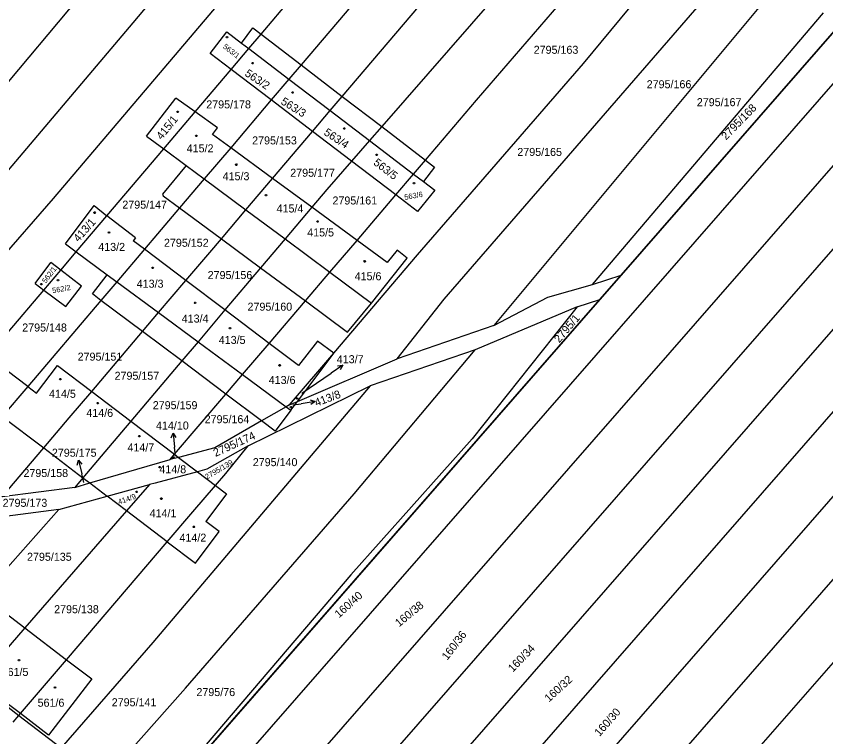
# Model space of a CAD drawing. Extents: x -580630 to -576196, y -1189024 to -1183567.
# Drawn here: x -578865 to -578693.1, y -1186221.6 to -1186068.5 of the extents above; entities that cross this region are included whole.
import ezdxf

# ---------------------------------------------------------------- set-up
doc = ezdxf.new("R2010")
doc.units = 0
for name, color, linetype in [('Vrstva 1', 7, 'Continuous'), ('Vrstva 16', 7, 'Continuous'), ('Vrstva 18', 7, 'Continuous'), ('Vrstva 19', 7, 'Continuous'), ('Vrstva 25', 7, 'Continuous'), ('Vrstva 4', 7, 'Continuous'), ('Vrstva 6', 7, 'Continuous'), ('Vrstva 63', 7, 'Continuous')]:
    doc.layers.add(name, color=color, linetype=linetype)

msp = doc.modelspace()

# ---------------------------------------------------------------- linework, layer by layer
at = {"layer": 'Vrstva 1'}
for p, q in [((-578817.1, -1186074.27), (-578814.71, -1186071.04)), ((-578814.71, -1186071.04), (-578812.98, -1186072.37)), ((-578736.53, -1186123.56), (-578690.23, -1186070.53)), ((-578898.26, -1186319.71), (-578682.45, -1186072.52)), ((-578823.75, -1186076.47), (-578820.28, -1186071.85)), ((-578820.28, -1186071.85), (-578817.1, -1186074.27)), ((-578812.98, -1186072.37), (-578804.48, -1186078.89)), ((-578819.32, -1186079.85), (-578823.75, -1186076.47)), ((-578810.8, -1186086.34), (-578819.32, -1186079.85)), ((-578804.48, -1186078.89), (-578795.74, -1186085.59)), ((-578673.98, -1186080.14), (-578889.37, -1186326.86)), ((-578837.31, -1186094.03), (-578831.04, -1186085.95)), ((-578826.97, -1186088.87), (-578831.04, -1186085.95)), ((-578802.05, -1186093.01), (-578810.8, -1186086.34)), ((-578795.74, -1186085.59), (-578787.37, -1186092.01)), ((-578880.26, -1186334.2), (-578664.84, -1186087.45)), ((-578822.23, -1186092.27), (-578826.97, -1186088.87)), ((-578823.3, -1186093.65), (-578822.23, -1186092.27)), ((-578819.42, -1186096.5), (-578823.3, -1186093.65)), ((-578793.75, -1186099.33), (-578802.05, -1186093.01)), ((-578787.37, -1186092.01), (-578778.08, -1186099.13)), ((-578656.06, -1186094.36), (-578871.56, -1186341.19)), ((-578837.31, -1186094.03), (-578833.65, -1186096.74)), ((-578833.65, -1186096.74), (-578828.87, -1186100.28)), ((-578810.54, -1186103.01), (-578819.42, -1186096.5)), ((-578828.87, -1186100.28), (-578833.87, -1186106.34)), ((-578784.35, -1186106.49), (-578793.75, -1186099.33)), ((-578778.08, -1186099.13), (-578776.12, -1186100.63)), ((-578646.98, -1186101.49), (-578862.56, -1186348.43)), ((-578776.12, -1186100.63), (-578778.47, -1186103.69)), ((-578802.19, -1186109.13), (-578810.54, -1186103.01)), ((-578778.47, -1186103.69), (-578776.08, -1186105.49)), ((-578776.08, -1186105.49), (-578779.75, -1186110)), ((-578833.87, -1186106.34), (-578833.76, -1186106.68)), ((-578833.76, -1186106.68), (-578830.26, -1186109.27)), ((-578779.75, -1186110), (-578784.35, -1186106.49)), ((-578854.52, -1186116.88), (-578848.44, -1186108.79)), ((-578853.31, -1186355.88), (-578637.63, -1186108.83)), ((-578848.44, -1186108.79), (-578845.69, -1186110.93)), ((-578792.6, -1186116.16), (-578802.19, -1186109.13)), ((-578830.26, -1186109.27), (-578821.41, -1186115.82)), ((-578839.64, -1186115.65), (-578845.69, -1186110.93)), ((-578842.88, -1186361.56), (-578628.42, -1186115.91)), ((-578839.64, -1186115.65), (-578840.11, -1186116.25)), ((-578821.41, -1186115.82), (-578813.07, -1186121.99)), ((-578854.52, -1186116.88), (-578852.2, -1186118.6)), ((-578837.73, -1186118.05), (-578840.11, -1186116.25)), ((-578786.19, -1186120.86), (-578792.6, -1186116.16)), ((-578852.2, -1186118.6), (-578845.64, -1186123.45)), ((-578828.94, -1186124.69), (-578837.73, -1186118.05)), ((-578784.08, -1186118.24), (-578786.19, -1186120.86)), ((-578781.97, -1186119.92), (-578784.08, -1186118.24)), ((-578860.95, -1186125.29), (-578857.59, -1186120.87)), ((-578855.49, -1186122.48), (-578857.59, -1186120.87)), ((-578789.52, -1186129.52), (-578781.97, -1186119.92)), ((-578851.07, -1186125.88), (-578855.49, -1186122.48)), ((-578619.17, -1186122.91), (-578828.84, -1186363.08)), ((-578813.07, -1186121.99), (-578803.56, -1186129.02)), ((-578848.79, -1186127.53), (-578845.64, -1186123.45)), ((-578741.03, -1186128.72), (-578736.53, -1186123.56)), ((-578860.95, -1186125.29), (-578859.08, -1186126.71)), ((-578854.42, -1186130.23), (-578851.07, -1186125.88)), ((-578820.65, -1186130.95), (-578828.94, -1186124.69)), ((-578859.08, -1186126.71), (-578854.42, -1186130.23)), ((-578846.97, -1186128.9), (-578848.79, -1186127.53)), ((-578838.14, -1186135.53), (-578846.97, -1186128.9)), ((-578819.05, -1186218.09), (-578741.03, -1186128.72)), ((-578803.56, -1186129.02), (-578794.61, -1186135.64)), ((-578794.61, -1186135.64), (-578789.52, -1186129.52)), ((-578811.25, -1186138.05), (-578820.65, -1186130.95)), ((-578829.81, -1186141.78), (-578838.14, -1186135.53)), ((-578805, -1186142.77), (-578811.25, -1186138.05)), ((-578801.03, -1186137.56), (-578805, -1186142.77)), ((-578797.55, -1186140.11), (-578801.03, -1186137.56)), ((-578801.52, -1186145.4), (-578797.55, -1186140.11)), ((-578862.53, -1186147.18), (-578871.07, -1186140.7)), ((-578820.44, -1186148.82), (-578829.81, -1186141.78)), ((-578860.64, -1186148.61), (-578856.2, -1186142.74)), ((-578856.2, -1186142.74), (-578848.94, -1186148.24)), ((-578805.25, -1186150.36), (-578801.52, -1186145.4)), ((-578862.53, -1186147.18), (-578860.64, -1186148.61)), ((-578848.94, -1186148.24), (-578840.62, -1186154.56)), ((-578812.87, -1186154.5), (-578820.44, -1186148.82)), ((-578806.66, -1186152.24), (-578805.25, -1186150.36)), ((-578867.95, -1186153.54), (-578859.13, -1186160.24)), ((-578806.66, -1186152.24), (-578809.97, -1186156.68)), ((-578840.62, -1186154.56), (-578831.34, -1186161.6)), ((-578809.97, -1186156.68), (-578812.87, -1186154.5)), ((-578859.13, -1186160.24), (-578850.79, -1186166.58)), ((-578831.34, -1186161.6), (-578830.49, -1186162.25)), ((-578830.49, -1186162.25), (-578826.45, -1186165.32)), ((-578826.45, -1186165.32), (-578822.64, -1186168.21)), ((-578850.79, -1186166.58), (-578849.32, -1186167.69)), ((-578849.32, -1186167.69), (-578845.63, -1186170.5)), ((-578822.64, -1186168.21), (-578820.29, -1186170)), ((-578841.54, -1186173.61), (-578845.63, -1186170.5)), ((-578820.29, -1186170), (-578824.68, -1186175.91)), ((-578832.89, -1186180.19), (-578841.54, -1186173.61)), ((-578821.89, -1186178.02), (-578824.68, -1186175.91)), ((-578826.93, -1186184.73), (-578821.89, -1186178.02)), ((-578832.89, -1186180.19), (-578826.93, -1186184.73)), ((-578872.13, -1186191.63), (-578863.14, -1186198.48)), ((-578863.14, -1186198.48), (-578854.3, -1186205.24)), ((-578854.3, -1186205.24), (-578848.94, -1186209.32)), ((-578873.33, -1186210.21), (-578864.4, -1186217.07)), ((-578864.08, -1186216.69), (-578873.04, -1186209.87)), ((-578848.94, -1186209.32), (-578858.08, -1186221.23)), ((-578864.4, -1186217.07), (-578855.44, -1186223.96)), ((-578858.08, -1186221.23), (-578864.08, -1186216.69)), ((-578836.72, -1186238.33), (-578819.05, -1186218.09))]:
    msp.add_line(p, q, dxfattribs=at)
at = {"layer": 'Vrstva 16'}
for p, q in [((-578795.632, -1186142.67), (-578798.11, -1186144.36)), ((-578804.32, -1186148.59), (-578798.11, -1186144.36)), ((-578801.519, -1186150.37), (-578804.48, -1186150.85)), ((-578806.21, -1186151.13), (-578804.48, -1186150.85)), ((-578831.654, -1186157.087), (-578831.34, -1186160.07)), ((-578831.14, -1186161.98), (-578831.34, -1186160.07)), ((-578851.766, -1186162.847), (-578851.05, -1186165.76)), ((-578850.6, -1186167.56), (-578851.05, -1186165.76))]:
    msp.add_line(p, q, dxfattribs=at)
for points in [[(-578796.74, -1186142.82), (-578795.632, -1186142.67), (-578796.176, -1186143.646)], [(-578802.586, -1186150.037), (-578801.519, -1186150.37), (-578802.426, -1186151.024)], [(-578832.047, -1186158.133), (-578831.654, -1186157.087), (-578831.052, -1186158.029)], [(-578852.013, -1186163.937), (-578851.766, -1186162.847), (-578851.042, -1186163.698)]]:
    msp.add_lwpolyline(points, dxfattribs=at)
at = {"layer": 'Vrstva 25'}
for points in [[(-578820.13, -1186072.84), (-578820.04, -1186072.99), (-578820.13, -1186073.14), (-578820.31, -1186073.14), (-578820.4, -1186072.99), (-578820.31, -1186072.84)], [(-578814.69, -1186078.38), (-578814.6, -1186078.53), (-578814.69, -1186078.68), (-578814.87, -1186078.68), (-578814.96, -1186078.53), (-578814.87, -1186078.38)], [(-578806.21, -1186084.6), (-578806.12, -1186084.75), (-578806.21, -1186084.9), (-578806.39, -1186084.9), (-578806.48, -1186084.75), (-578806.39, -1186084.6)], [(-578830.59, -1186088.7), (-578830.5, -1186088.85), (-578830.59, -1186089), (-578830.77, -1186089), (-578830.86, -1186088.85), (-578830.77, -1186088.7)], [(-578795.23, -1186092.26), (-578795.14, -1186092.41), (-578795.23, -1186092.56), (-578795.41, -1186092.56), (-578795.5, -1186092.41), (-578795.41, -1186092.26)], [(-578826.65, -1186093.82), (-578826.56, -1186093.97), (-578826.65, -1186094.12), (-578826.83, -1186094.12), (-578826.92, -1186093.97), (-578826.83, -1186093.82)], [(-578788.33, -1186097.87), (-578788.24, -1186098.02), (-578788.33, -1186098.17), (-578788.51, -1186098.17), (-578788.6, -1186098.02), (-578788.51, -1186097.87)], [(-578818.16, -1186099.94), (-578818.07, -1186100.09), (-578818.16, -1186100.24), (-578818.34, -1186100.24), (-578818.43, -1186100.09), (-578818.34, -1186099.94)], [(-578780.41, -1186103.84), (-578780.32, -1186103.99), (-578780.41, -1186104.14), (-578780.59, -1186104.14), (-578780.68, -1186103.99), (-578780.59, -1186103.84)], [(-578811.83, -1186106.43), (-578811.74, -1186106.58), (-578811.83, -1186106.73), (-578812.01, -1186106.73), (-578812.1, -1186106.58), (-578812.01, -1186106.43)], [(-578848.24, -1186110.13), (-578848.15, -1186110.28), (-578848.24, -1186110.43), (-578848.42, -1186110.43), (-578848.51, -1186110.28), (-578848.42, -1186110.13)], [(-578800.89, -1186112.01), (-578800.8, -1186112.16), (-578800.89, -1186112.31), (-578801.07, -1186112.31), (-578801.16, -1186112.16), (-578801.07, -1186112.01)], [(-578845.19, -1186114.36), (-578845.1, -1186114.51), (-578845.19, -1186114.66), (-578845.37, -1186114.66), (-578845.46, -1186114.51), (-578845.37, -1186114.36)], [(-578790.87, -1186120.47), (-578790.78, -1186120.62), (-578790.87, -1186120.77), (-578791.05, -1186120.77), (-578791.14, -1186120.62), (-578791.05, -1186120.47)], [(-578835.91, -1186121.86), (-578835.82, -1186122.01), (-578835.91, -1186122.16), (-578836.09, -1186122.16), (-578836.18, -1186122.01), (-578836.09, -1186121.86)], [(-578855.99, -1186124.48), (-578855.9, -1186124.63), (-578855.99, -1186124.78), (-578856.17, -1186124.78), (-578856.26, -1186124.63), (-578856.17, -1186124.48)], [(-578859.55, -1186125.33), (-578859.46, -1186125.48), (-578859.55, -1186125.63), (-578859.73, -1186125.63), (-578859.82, -1186125.48), (-578859.73, -1186125.33)], [(-578826.89, -1186129.26), (-578826.8, -1186129.41), (-578826.89, -1186129.56), (-578827.07, -1186129.56), (-578827.16, -1186129.41), (-578827.07, -1186129.26)], [(-578819.5, -1186134.64), (-578819.41, -1186134.79), (-578819.5, -1186134.94), (-578819.68, -1186134.94), (-578819.77, -1186134.79), (-578819.68, -1186134.64)], [(-578808.94, -1186142.56), (-578808.85, -1186142.71), (-578808.94, -1186142.86), (-578809.12, -1186142.86), (-578809.21, -1186142.71), (-578809.12, -1186142.56)], [(-578855.49, -1186145.5), (-578855.4, -1186145.65), (-578855.49, -1186145.8), (-578855.67, -1186145.8), (-578855.76, -1186145.65), (-578855.67, -1186145.5)], [(-578805.27, -1186149.62), (-578805.18, -1186149.77), (-578805.27, -1186149.92), (-578805.45, -1186149.92), (-578805.54, -1186149.77), (-578805.45, -1186149.62)], [(-578847.56, -1186150.6), (-578847.47, -1186150.75), (-578847.56, -1186150.9), (-578847.74, -1186150.9), (-578847.83, -1186150.75), (-578847.74, -1186150.6)], [(-578806.56, -1186151.43), (-578806.47, -1186151.58), (-578806.56, -1186151.73), (-578806.74, -1186151.73), (-578806.83, -1186151.58), (-578806.74, -1186151.43)], [(-578838.74, -1186157.6), (-578838.65, -1186157.75), (-578838.74, -1186157.9), (-578838.92, -1186157.9), (-578839.01, -1186157.75), (-578838.92, -1186157.6)], [(-578831.54, -1186162.17), (-578831.45, -1186162.32), (-578831.54, -1186162.47), (-578831.72, -1186162.47), (-578831.81, -1186162.32), (-578831.72, -1186162.17)], [(-578834.42, -1186164.21), (-578834.33, -1186164.36), (-578834.42, -1186164.51), (-578834.6, -1186164.51), (-578834.69, -1186164.36), (-578834.6, -1186164.21)], [(-578839.33, -1186169.45), (-578839.24, -1186169.6), (-578839.33, -1186169.75), (-578839.51, -1186169.75), (-578839.6, -1186169.6), (-578839.51, -1186169.45)], [(-578834.05, -1186170.88), (-578833.96, -1186171.03), (-578834.05, -1186171.18), (-578834.23, -1186171.18), (-578834.32, -1186171.03), (-578834.23, -1186170.88)], [(-578827.16, -1186176.84), (-578827.07, -1186176.99), (-578827.16, -1186177.14), (-578827.34, -1186177.14), (-578827.43, -1186176.99), (-578827.34, -1186176.84)], [(-578864.28, -1186205.16), (-578864.19, -1186205.31), (-578864.28, -1186205.46), (-578864.46, -1186205.46), (-578864.55, -1186205.31), (-578864.46, -1186205.16)], [(-578856.63, -1186210.99), (-578856.54, -1186211.14), (-578856.63, -1186211.29), (-578856.81, -1186211.29), (-578856.9, -1186211.14), (-578856.81, -1186210.99)]]:
    msp.add_lwpolyline(points, close=True, dxfattribs=at)
at = {"layer": 'Vrstva 4'}
for p, q in [((-578817.1, -1186074.27), (-578815.58, -1186075.43)), ((-578815.58, -1186075.43), (-578807.06, -1186081.93)), ((-578807.06, -1186081.93), (-578798.3, -1186088.6)), ((-578798.3, -1186088.6), (-578789.94, -1186094.96)), ((-578789.94, -1186094.96), (-578780.59, -1186102.08)), ((-578828.87, -1186100.28), (-578825.04, -1186103.12)), ((-578780.59, -1186102.08), (-578778.47, -1186103.69)), ((-578825.04, -1186103.12), (-578816.2, -1186109.68)), ((-578816.2, -1186109.68), (-578807.88, -1186115.86)), ((-578807.88, -1186115.86), (-578798.37, -1186122.93)), ((-578798.37, -1186122.93), (-578789.52, -1186129.52)), ((-578845.64, -1186123.45), (-578843.61, -1186124.95)), ((-578843.61, -1186124.95), (-578834.72, -1186131.5)), ((-578834.72, -1186131.5), (-578826.35, -1186137.69)), ((-578826.35, -1186137.69), (-578816.89, -1186144.66)), ((-578816.89, -1186144.66), (-578807.66, -1186151.5)), ((-578807.66, -1186151.5), (-578806.66, -1186152.24))]:
    msp.add_line(p, q, dxfattribs=at)
at = {"layer": 'Vrstva 6'}
for p, q in [((-578840.14, -1186069.93), (-578782.94, -1186002.05)), ((-578754.18, -1186019.62), (-578804.48, -1186078.89)), ((-578795.74, -1186085.59), (-578745.55, -1186026.48)), ((-578736.53, -1186033.66), (-578787.37, -1186092.01)), ((-578799.28, -1186039.11), (-578857.1, -1186107.27)), ((-578767.23, -1186086.41), (-578727.81, -1186040.6)), ((-578836.31, -1186046.32), (-578883.67, -1186102.55)), ((-578744.5, -1186078.58), (-578718.99, -1186047.61)), ((-578702.44, -1186060.8), (-578763.58, -1186134.25)), ((-578812.98, -1186072.37), (-578805.6, -1186063.66)), ((-578774.07, -1186128.66), (-578717.84, -1186063.7)), ((-578742.58, -1186125.54), (-578693.58, -1186067.86)), ((-578876.69, -1186113.14), (-578840.14, -1186069.93)), ((-578815.58, -1186075.43), (-578812.98, -1186072.37)), ((-578819.32, -1186079.85), (-578815.58, -1186075.43)), ((-578826.97, -1186088.87), (-578819.32, -1186079.85)), ((-578804.48, -1186078.89), (-578807.06, -1186081.93)), ((-578779.79, -1186119.21), (-578744.5, -1186078.58)), ((-578807.06, -1186081.93), (-578810.8, -1186086.34)), ((-578810.8, -1186086.34), (-578819.42, -1186096.5)), ((-578798.3, -1186088.6), (-578795.74, -1186085.59)), ((-578778.08, -1186099.13), (-578767.23, -1186086.41)), ((-578833.65, -1186096.74), (-578826.97, -1186088.87)), ((-578802.05, -1186093.01), (-578798.3, -1186088.6)), ((-578810.54, -1186103.01), (-578802.05, -1186093.01)), ((-578787.37, -1186092.01), (-578789.94, -1186094.96)), ((-578789.94, -1186094.96), (-578793.75, -1186099.33)), ((-578845.69, -1186110.93), (-578833.65, -1186096.74)), ((-578819.42, -1186096.5), (-578825.04, -1186103.12)), ((-578793.75, -1186099.33), (-578798.98, -1186105.34)), ((-578780.59, -1186102.08), (-578778.08, -1186099.13)), ((-578784.35, -1186106.49), (-578780.59, -1186102.08)), ((-578825.04, -1186103.12), (-578830.26, -1186109.27)), ((-578816.2, -1186109.68), (-578810.54, -1186103.01)), ((-578798.98, -1186105.34), (-578802.19, -1186109.13)), ((-578857.1, -1186107.27), (-578917.5, -1186176.3)), ((-578792.6, -1186116.16), (-578784.35, -1186106.49)), ((-578802.19, -1186109.13), (-578807.88, -1186115.86)), ((-578830.26, -1186109.27), (-578834.97, -1186114.81)), ((-578821.41, -1186115.82), (-578816.2, -1186109.68)), ((-578852.2, -1186118.6), (-578845.69, -1186110.93)), ((-578834.97, -1186114.81), (-578837.73, -1186118.05)), ((-578823.86, -1186118.71), (-578821.41, -1186115.82)), ((-578807.88, -1186115.86), (-578813.07, -1186121.99)), ((-578798.37, -1186122.93), (-578792.6, -1186116.16)), ((-578855.49, -1186122.48), (-578852.2, -1186118.6)), ((-578837.73, -1186118.05), (-578843.61, -1186124.95)), ((-578828.94, -1186124.69), (-578823.86, -1186118.71)), ((-578797.55, -1186140.11), (-578779.79, -1186119.21)), ((-578859.08, -1186126.71), (-578855.49, -1186122.48)), ((-578813.07, -1186121.99), (-578820.65, -1186130.95)), ((-578803.56, -1186129.02), (-578798.37, -1186122.93)), ((-578742.58, -1186125.54), (-578736.53, -1186123.56)), ((-578843.61, -1186124.95), (-578846.97, -1186128.9)), ((-578834.72, -1186131.5), (-578828.94, -1186124.69)), ((-578752.06, -1186128.2), (-578742.58, -1186125.54)), ((-578866.69, -1186135.68), (-578859.08, -1186126.71)), ((-578846.97, -1186128.9), (-578862.53, -1186147.18)), ((-578811.25, -1186138.05), (-578803.56, -1186129.02)), ((-578784.08, -1186141.3), (-578774.07, -1186128.66)), ((-578763.58, -1186134.25), (-578752.06, -1186128.2)), ((-578745.84, -1186130.29), (-578741.03, -1186128.72)), ((-578838.14, -1186135.53), (-578834.72, -1186131.5)), ((-578820.65, -1186130.95), (-578826.35, -1186137.69)), ((-578745.84, -1186130.29), (-578768.13, -1186158.35)), ((-578745.84, -1186130.29), (-578767.5, -1186139.42)), ((-578763.58, -1186134.25), (-578784.08, -1186141.3)), ((-578848.94, -1186148.24), (-578838.14, -1186135.53)), ((-578826.35, -1186137.69), (-578829.81, -1186141.78)), ((-578816.89, -1186144.66), (-578811.25, -1186138.05)), ((-578806.95, -1186151.09), (-578797.55, -1186140.11)), ((-578793.2, -1186170), (-578767.5, -1186139.42)), ((-578767.5, -1186139.42), (-578789.78, -1186147.09)), ((-578829.81, -1186141.78), (-578840.62, -1186154.56)), ((-578805.25, -1186150.36), (-578784.08, -1186141.3)), ((-578820.44, -1186148.82), (-578816.89, -1186144.66)), ((-578862.53, -1186147.18), (-578867.95, -1186153.54)), ((-578853.72, -1186153.87), (-578848.94, -1186148.24)), ((-578789.78, -1186147.09), (-578835.97, -1186201.55)), ((-578815.75, -1186159.77), (-578789.78, -1186147.09)), ((-578831.34, -1186161.6), (-578820.44, -1186148.82)), ((-578806.95, -1186151.09), (-578805.25, -1186150.36)), ((-578807.66, -1186151.5), (-578812.87, -1186154.5)), ((-578806.95, -1186151.09), (-578807.66, -1186151.5)), ((-578859.13, -1186160.24), (-578853.72, -1186153.87)), ((-578840.62, -1186154.56), (-578845.39, -1186160.19)), ((-578812.87, -1186154.5), (-578822.76, -1186160.21)), ((-578768.13, -1186158.35), (-578793.92, -1186187.22)), ((-578867.98, -1186170.66), (-578859.13, -1186160.24)), ((-578845.39, -1186160.19), (-578850.79, -1186166.58)), ((-578822.76, -1186160.21), (-578830.49, -1186162.25)), ((-578815.75, -1186159.77), (-578824.46, -1186164.79)), ((-578820.48, -1186165.68), (-578815.75, -1186159.77)), ((-578832.3, -1186162.73), (-578831.34, -1186161.6)), ((-578830.49, -1186162.25), (-578832.3, -1186162.73)), ((-578839.34, -1186164.78), (-578832.3, -1186162.73)), ((-578849.32, -1186167.69), (-578839.34, -1186164.78)), ((-578826.45, -1186165.32), (-578835.47, -1186167.7)), ((-578824.46, -1186164.79), (-578826.45, -1186165.32)), ((-578822.64, -1186168.21), (-578820.48, -1186165.68)), ((-578850.79, -1186166.58), (-578852.53, -1186168.63)), ((-578852.53, -1186168.63), (-578867.98, -1186170.66)), ((-578852.53, -1186168.63), (-578849.32, -1186167.69)), ((-578845.63, -1186170.5), (-578836.68, -1186168.02)), ((-578836.68, -1186168.02), (-578841.54, -1186173.61)), ((-578835.47, -1186167.7), (-578836.68, -1186168.02)), ((-578827.44, -1186173.82), (-578822.64, -1186168.21)), ((-578855.88, -1186173.34), (-578845.63, -1186170.5)), ((-578829.02, -1186211.28), (-578793.2, -1186170)), ((-578872.13, -1186191.63), (-578855.88, -1186173.34)), ((-578855.88, -1186173.34), (-578872.04, -1186175.45)), ((-578841.54, -1186173.61), (-578863.14, -1186198.48)), ((-578832.89, -1186180.19), (-578827.44, -1186173.82)), ((-578854.3, -1186205.24), (-578832.89, -1186180.19)), ((-578793.92, -1186187.22), (-578829.06, -1186228.43)), ((-578863.14, -1186198.48), (-578873.04, -1186209.87)), ((-578835.97, -1186201.55), (-578855.44, -1186223.96)), ((-578864.08, -1186216.69), (-578854.3, -1186205.24)), ((-578846.43, -1186230.88), (-578829.02, -1186211.28)), ((-578865.63, -1186218.51), (-578864.4, -1186217.07)), ((-578864.4, -1186217.07), (-578864.08, -1186216.69))]:
    msp.add_line(p, q, dxfattribs=at)
at = {"layer": 'Vrstva 63'}
for p, q in [((-578690.23, -1186070.53), (-578736.53, -1186123.56)), ((-578736.53, -1186123.56), (-578741.03, -1186128.72)), ((-578741.03, -1186128.72), (-578836.72, -1186238.33))]:
    msp.add_line(p, q, dxfattribs=at)

# ---------------------------------------------------------------- texts
at = {"layer": 'Vrstva 16'}
for s, p in [('413/7', (-578796.902, -1186142.25)), ('414/10', (-578835.283, -1186156.34)), ('2795/175', (-578857.39, -1186162.12))]:
    msp.add_text(s, height=1.7, dxfattribs=at).set_placement(p)
msp.add_text('413/8', height=1.7, rotation=20.56919, dxfattribs=at).set_placement((-578801.219, -1186151.492))
at = {"layer": 'Vrstva 18'}
for s, height, p in [('2795/163', 1.7, (-578755.1, -1186076.53)), ('2795/166', 1.7, (-578731.103, -1186083.85)), ('2795/178', 1.7, (-578824.613, -1186088.13)), ('2795/167', 1.7, (-578720.463, -1186087.66)), ('2795/153', 1.7, (-578814.867, -1186095.78)), ('2795/165', 1.7, (-578758.57, -1186098.23)), ('2795/177', 1.7, (-578806.783, -1186102.65)), ('2795/161', 1.7, (-578797.815, -1186108.54)), ('2795/147', 1.7, (-578842.433, -1186109.43)), ('2795/152', 1.7, (-578833.594, -1186117.52)), ('2795/156', 1.7, (-578824.32, -1186124.38)), ('2795/160', 1.7, (-578815.85, -1186131.1)), ('2795/148', 1.7, (-578863.683, -1186135.52)), ('2795/151', 1.7, (-578851.922, -1186141.71)), ('2795/157', 1.7, (-578844.08, -1186145.77)), ('2795/159', 1.7, (-578835.97, -1186152.02)), ('2795/164', 1.7, (-578824.953, -1186155)), ('2795/140', 1.7, (-578814.74, -1186164.12)), ('2795/158', 1.7, (-578863.43, -1186166.43)), ('2795/175', 0.1, (-578850.908, -1186167.56)), ('2795/173', 1.7, (-578867.85, -1186172.76)), ('2795/135', 1.7, (-578862.667, -1186184.22)), ('2795/138', 1.7, (-578856.911, -1186195.36)), ('2795/76', 1.7, (-578826.702, -1186212.96)), ('2795/141', 1.7, (-578844.685, -1186215.12))]:
    msp.add_text(s, height=height, dxfattribs=at).set_placement(p)
for s, height, rotation, p in [('2795/168', 1.7, 45.72203, (-578714.248, -1186094.961)), ('2795/1', 1.7, 49.44626, (-578749.666, -1186138.039)), ('2795/174', 1.7, 24.52259, (-578822.645, -1186162.175)), ('2795/139', 1.14, 30.48136, (-578824.475, -1186166.98)), ('160/40', 1.7, 41.99781, (-578796.435, -1186196.471)), ('160/38', 1.7, 39.3622, (-578783.672, -1186198.359)), ('160/36', 1.7, 52.65482, (-578773.439, -1186205.451)), ('160/34', 1.7, 45.83662, (-578759.519, -1186207.979)), ('160/32', 1.7, 42.28429, (-578751.861, -1186214.336)), ('160/30', 1.7, 48.70141, (-578741.104, -1186221.651))]:
    msp.add_text(s, height=height, rotation=rotation, dxfattribs=at).set_placement(p)
at = {"layer": 'Vrstva 19'}
for s, height, rotation, p in [('563/1', 1.14, 322.34606, (-578821.179, -1186075.211)), ('563/2', 1.7, 326.29946, (-578816.579, -1186081.08)), ('563/3', 1.7, 328.24752, (-578808.937, -1186087.097)), ('415/1', 1.7, 50.93595, (-578834.084, -1186094.912)), ('563/4', 1.7, 326.58594, (-578799.797, -1186093.626)), ('563/5', 1.7, 322.57524, (-578789.27, -1186099.954)), ('563/6', 1.14, 10.08406, (-578782.455, -1186107.589)), ('413/1', 1.7, 48.07116, (-578851.747, -1186116.641)), ('562/1', 1.14, 52.9413, (-578858.685, -1186125.395)), ('562/2', 1.14, 10.59972, (-578857.211, -1186127.407)), ('414/9', 1.14, 19.82434, (-578843.116, -1186172.312))]:
    msp.add_text(s, height=height, rotation=rotation, dxfattribs=at).set_placement(p)
for s, height, p in [('415/2', 1.7, (-578828.766, -1186097.47)), ('415/3', 1.7, (-578821.139, -1186103.39)), ('415/4', 1.7, (-578809.682, -1186110.24)), ('415/5', 1.7, (-578803.179, -1186115.33)), ('413/2', 1.7, (-578847.546, -1186118.4)), ('415/6', 1.7, (-578793.112, -1186124.64)), ('413/3', 1.7, (-578839.379, -1186126.22)), ('413/4', 1.7, (-578829.822, -1186133.62)), ('413/5', 1.7, (-578821.959, -1186138.16)), ('413/6', 1.7, (-578811.352, -1186146.66)), ('414/5', 1.7, (-578857.992, -1186149.6)), ('413/7', 0.1, (-578804.504, -1186148.59)), ('414/6', 1.7, (-578850.075, -1186153.66)), ('413/8', 0.1, (-578806.398, -1186151.13)), ('414/7', 1.7, (-578841.345, -1186160.99)), ('414/10', 0.1, (-578831.343, -1186161.98)), ('414/8', 1.7, (-578834.565, -1186165.63)), ('414/1', 1.7, (-578836.647, -1186174.98)), ('414/2', 1.7, (-578830.299, -1186180.16)), ('561/5', 1.7, (-578868.059, -1186208.68)), ('561/6', 1.7, (-578860.422, -1186215.22))]:
    msp.add_text(s, height=height, dxfattribs=at).set_placement(p)

doc.saveas('drawing.dxf')
